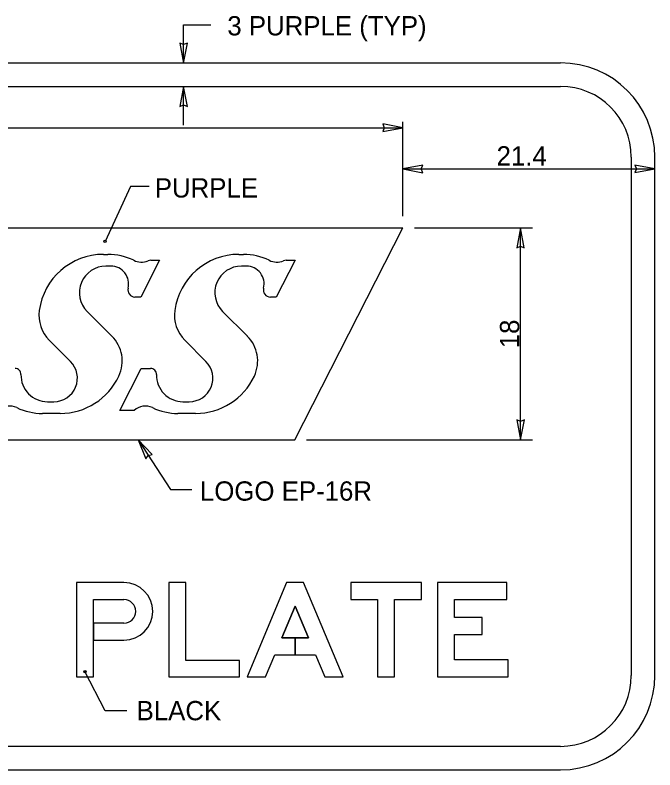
# Model space of a CAD drawing. Extents: x 319706 to 320346, y 1621790 to 1622121.
# Drawn here: x 319803.6 to 319850, y 1621939.2 to 1621994 of the extents above; entities that cross this region are included whole.
import ezdxf

# ---------------------------------------------------------------- set-up
doc = ezdxf.new("R2010")
doc.units = 0
for name, color, linetype in [('1', 7, 'Continuous'), ('52', 7, 'Continuous'), ('GSBWFill', 7, 'Continuous'), ('GSColorFill', 7, 'Continuous'), ('GSOutline', 7, 'Continuous'), ('SignPanel', 7, 'Continuous')]:
    doc.layers.add(name, color=color, linetype=linetype)

msp = doc.modelspace()

# ---------------------------------------------------------------- linework, layer by layer
at = {"layer": '1'}
for p, q in [((319815.814, 1621993.311), (319817.798, 1621993.298)), ((319815.814, 1621990.526), (319815.814, 1621993.311)), ((319815.814, 1621986.016), (319815.814, 1621988.829)), ((319831.717, 1621979.425), (319831.717, 1621986.265)), ((319794.612, 1621985.838), (319831.717, 1621985.838)), ((319831.717, 1621982.845), (319850.014, 1621982.845)), ((319811.95, 1621981.567), (319810.107, 1621977.589)), ((319813.308, 1621981.567), (319811.95, 1621981.567)), ((319832.572, 1621978.569), (319841.122, 1621978.569)), ((319840.267, 1621963.179), (319840.267, 1621978.569)), ((319812.512, 1621963.179), (319814.868, 1621959.581)), ((319824.73, 1621963.179), (319841.122, 1621963.179)), ((319814.868, 1621959.581), (319816.416, 1621959.581)), ((319810.118, 1621943.512), (319808.646, 1621946.366)), ((319811.68, 1621943.512), (319810.118, 1621943.512))]:
    msp.add_line(p, q, dxfattribs=at)
for centre in [(319810.107, 1621977.588), (319808.646, 1621946.366)]:
    msp.add_circle(centre, 0.0855, dxfattribs=at)
at = {"layer": '52'}
for p, q in [((319815.814, 1621991.866), (319815.544, 1621991.976)), ((319815.544, 1621991.976), (319815.814, 1621990.526)), ((319815.814, 1621990.526), (319816.094, 1621991.976)), ((319816.094, 1621991.976), (319815.814, 1621991.866)), ((319815.814, 1621988.829), (319815.534, 1621987.379)), ((319816.084, 1621987.379), (319815.814, 1621988.829)), ((319815.534, 1621987.379), (319815.814, 1621987.489)), ((319815.814, 1621987.489), (319816.084, 1621987.379)), ((319831.717, 1621985.838), (319830.267, 1621986.118)), ((319830.267, 1621986.118), (319830.377, 1621985.838)), ((319830.377, 1621985.838), (319830.267, 1621985.568)), ((319830.267, 1621985.568), (319831.717, 1621985.838)), ((319833.167, 1621983.115), (319831.717, 1621982.845)), ((319833.057, 1621982.845), (319833.167, 1621983.115)), ((319850.014, 1621982.845), (319848.564, 1621983.125)), ((319848.564, 1621983.125), (319848.674, 1621982.845)), ((319831.717, 1621982.845), (319833.167, 1621982.565)), ((319833.167, 1621982.565), (319833.057, 1621982.845)), ((319848.674, 1621982.845), (319848.564, 1621982.575)), ((319848.564, 1621982.575), (319850.014, 1621982.845)), ((319840.267, 1621978.569), (319839.987, 1621977.119)), ((319840.537, 1621977.119), (319840.267, 1621978.569)), ((319839.987, 1621977.119), (319840.267, 1621977.229)), ((319840.267, 1621977.229), (319840.537, 1621977.119)), ((319840.267, 1621964.519), (319839.997, 1621964.629)), ((319839.997, 1621964.629), (319840.267, 1621963.179)), ((319840.267, 1621963.179), (319840.547, 1621964.629)), ((319840.547, 1621964.629), (319840.267, 1621964.519)), ((319812.512, 1621963.179), (319813.072, 1621961.813)), ((319813.532, 1621962.114), (319812.512, 1621963.179)), ((319813.072, 1621961.813), (319813.246, 1621962.058)), ((319813.246, 1621962.058), (319813.532, 1621962.114))]:
    msp.add_line(p, q, dxfattribs=at)
at = {"layer": 'GSBWFill'}
msp.add_line((319809.262, 1621951.598), (319811.485, 1621951.598), dxfattribs=at)
for points in [[(319811.485, 1621952.829), (319808.03, 1621952.829), (319808.03, 1621945.988), (319809.262, 1621945.988), (319809.262, 1621951.598)], [(319811.485, 1621949.887), (319809.262, 1621949.887), (319809.262, 1621948.656), (319811.485, 1621948.656)]]:
    msp.add_lwpolyline(points, dxfattribs=at)
for points in [[(319819.866, 1621945.988), (319819.866, 1621947.185), (319815.966, 1621947.185), (319815.966, 1621952.829), (319814.735, 1621952.829), (319814.735, 1621945.988)], [(319824.864, 1621948.827), (319823.903, 1621948.827), (319823.903, 1621947.595), (319825.381, 1621947.595), (319826.056, 1621945.988), (319827.392, 1621945.988), (319824.518, 1621952.829), (319823.287, 1621952.829), (319820.413, 1621945.988), (319821.749, 1621945.988), (319822.424, 1621947.595), (319823.903, 1621947.595), (319823.903, 1621948.827), (319822.942, 1621948.827), (319823.903, 1621951.115)], [(319827.939, 1621951.598), (319829.889, 1621951.598), (319829.889, 1621945.988), (319831.121, 1621945.988), (319831.121, 1621951.598), (319833.07, 1621951.598), (319833.07, 1621952.829), (319827.939, 1621952.829)], [(319839.365, 1621947.219), (319835.465, 1621947.219), (319835.465, 1621949.059), (319837.483, 1621949.059), (319837.483, 1621950.291), (319835.465, 1621950.291), (319835.465, 1621951.598), (319839.262, 1621951.598), (319839.262, 1621952.829), (319834.233, 1621952.829), (319834.233, 1621945.988), (319839.365, 1621945.988)]]:
    msp.add_lwpolyline(points, close=True, dxfattribs=at)
for major_axis in [(0, 2.087), (0, 0.855)]:
    msp.add_ellipse((319811.485, 1621950.742), major_axis=major_axis, ratio=0.999994, start_param=3.141593, end_param=6.283185, dxfattribs=at)
at = {"layer": 'GSColorFill'}
msp.add_line((319809.262, 1621951.598), (319811.485, 1621951.598), dxfattribs=at)
for points in [[(319811.485, 1621952.829), (319808.03, 1621952.829), (319808.03, 1621945.988), (319809.262, 1621945.988), (319809.262, 1621951.598)], [(319811.485, 1621949.887), (319809.262, 1621949.887), (319809.262, 1621948.656), (319811.485, 1621948.656)]]:
    msp.add_lwpolyline(points, dxfattribs=at)
for points in [[(319819.866, 1621945.988), (319819.866, 1621947.185), (319815.966, 1621947.185), (319815.966, 1621952.829), (319814.735, 1621952.829), (319814.735, 1621945.988)], [(319824.864, 1621948.827), (319823.903, 1621948.827), (319823.903, 1621947.595), (319825.381, 1621947.595), (319826.056, 1621945.988), (319827.392, 1621945.988), (319824.518, 1621952.829), (319823.287, 1621952.829), (319820.413, 1621945.988), (319821.749, 1621945.988), (319822.424, 1621947.595), (319823.903, 1621947.595), (319823.903, 1621948.827), (319822.942, 1621948.827), (319823.903, 1621951.115)], [(319827.939, 1621951.598), (319829.889, 1621951.598), (319829.889, 1621945.988), (319831.121, 1621945.988), (319831.121, 1621951.598), (319833.07, 1621951.598), (319833.07, 1621952.829), (319827.939, 1621952.829)], [(319839.365, 1621947.219), (319835.465, 1621947.219), (319835.465, 1621949.059), (319837.483, 1621949.059), (319837.483, 1621950.291), (319835.465, 1621950.291), (319835.465, 1621951.598), (319839.262, 1621951.598), (319839.262, 1621952.829), (319834.233, 1621952.829), (319834.233, 1621945.988), (319839.365, 1621945.988)]]:
    msp.add_lwpolyline(points, close=True, dxfattribs=at)
for major_axis in [(0, 2.087), (0, 0.855)]:
    msp.add_ellipse((319811.485, 1621950.742), major_axis=major_axis, ratio=0.999994, start_param=3.141593, end_param=6.283185, dxfattribs=at)
at = {"layer": 'GSOutline'}
for p, q in [((319809.262, 1621951.598), (319811.485, 1621951.598)), ((319809.262, 1621948.656), (319811.485, 1621948.656))]:
    msp.add_line(p, q, dxfattribs=at)
for points in [[(319811.485, 1621952.829), (319808.03, 1621952.829), (319808.03, 1621945.988), (319809.262, 1621945.988), (319809.262, 1621948.656)], [(319811.485, 1621949.887), (319809.262, 1621949.887), (319809.262, 1621951.598)]]:
    msp.add_lwpolyline(points, dxfattribs=at)
for points in [[(319819.866, 1621945.988), (319819.866, 1621947.185), (319815.966, 1621947.185), (319815.966, 1621952.829), (319814.735, 1621952.829), (319814.735, 1621945.988)], [(319822.424, 1621947.595), (319825.381, 1621947.595), (319826.056, 1621945.988), (319827.392, 1621945.988), (319824.518, 1621952.829), (319823.287, 1621952.829), (319820.413, 1621945.988), (319821.749, 1621945.988)], [(319827.939, 1621951.598), (319829.889, 1621951.598), (319829.889, 1621945.988), (319831.121, 1621945.988), (319831.121, 1621951.598), (319833.07, 1621951.598), (319833.07, 1621952.829), (319827.939, 1621952.829)], [(319839.365, 1621947.219), (319835.465, 1621947.219), (319835.465, 1621949.059), (319837.483, 1621949.059), (319837.483, 1621950.291), (319835.465, 1621950.291), (319835.465, 1621951.598), (319839.262, 1621951.598), (319839.262, 1621952.829), (319834.233, 1621952.829), (319834.233, 1621945.988), (319839.365, 1621945.988)], [(319824.864, 1621948.827), (319823.903, 1621951.115), (319822.942, 1621948.827)]]:
    msp.add_lwpolyline(points, close=True, dxfattribs=at)
for major_axis in [(0, 2.087), (0, 0.855)]:
    msp.add_ellipse((319811.485, 1621950.742), major_axis=major_axis, ratio=0.999994, start_param=3.141593, end_param=6.283185, dxfattribs=at)
at = {"layer": 'SignPanel'}
for p, q in [((319733.734, 1621990.539), (319843.174, 1621990.539)), ((319733.734, 1621988.829), (319843.174, 1621988.829)), ((319848.304, 1621946.079), (319848.304, 1621983.699)), ((319850.014, 1621946.079), (319850.014, 1621983.699)), ((319782.943, 1621978.569), (319831.717, 1621978.569)), ((319823.875, 1621963.179), (319831.717, 1621978.569)), ((319809.997, 1621976.645), (319810.321, 1621976.645)), ((319819.83, 1621976.645), (319820.154, 1621976.645)), ((319814.064, 1621976.217), (319812.705, 1621973.551)), ((319813.423, 1621976.217), (319814.064, 1621976.217)), ((319823.897, 1621976.217), (319822.538, 1621973.551)), ((319823.255, 1621976.217), (319823.897, 1621976.217)), ((319810.538, 1621975.79), (319810.172, 1621975.79)), ((319820.371, 1621975.79), (319820.004, 1621975.79)), ((319812.705, 1621973.551), (319812.278, 1621973.551)), ((319822.538, 1621973.551), (319822.11, 1621973.551)), ((319808.811, 1621972.506), (319810.603, 1621970.714)), ((319818.644, 1621972.506), (319820.436, 1621970.714)), ((319807.603, 1621968.877), (319806.065, 1621970.415)), ((319817.436, 1621968.877), (319815.898, 1621970.415)), ((319811.175, 1621965.317), (319812.728, 1621968.364)), ((319812.728, 1621968.364), (319813.415, 1621968.364)), ((319805.932, 1621965.957), (319806.394, 1621965.957)), ((319815.765, 1621965.957), (319816.226, 1621965.957)), ((319806.854, 1621965.102), (319805.568, 1621965.102)), ((319812.214, 1621965.317), (319811.175, 1621965.317)), ((319816.686, 1621965.102), (319815.4, 1621965.102)), ((319781.809, 1621963.179), (319823.875, 1621963.179)), ((319733.734, 1621940.949), (319843.174, 1621940.949)), ((319733.734, 1621939.239), (319843.174, 1621939.239))]:
    msp.add_line(p, q, dxfattribs=at)
for centre, radius, start, end in [((319843.173, 1621983.698), 6.84, 0, 90), ((319843.173, 1621983.698), 5.13, 0, 90), ((319809.997, 1621971.942), 4.702, 90, 172.3089), ((319810.321, 1621972.369), 4.275, 64.0896, 90), ((319819.829, 1621971.942), 4.702, 90, 172.3089), ((319820.153, 1621972.369), 4.275, 64.0896, 90), ((319812.749, 1621977.368), 1.282, 244.0896, 292.0347), ((319813.423, 1621975.704), 0.513, 90, 112.0347), ((319822.582, 1621977.368), 1.282, 244.0896, 292.0347), ((319823.255, 1621975.704), 0.513, 90, 112.0347), ((319810.171, 1621973.865), 1.924, 90, 225), ((319810.538, 1621974.507), 1.282, 345.6915, 90), ((319820.004, 1621973.865), 1.924, 90, 225), ((319820.371, 1621974.507), 1.282, 345.6915, 90), ((319812.278, 1621974.063), 0.513, 165.6915, 270), ((319822.111, 1621974.063), 0.513, 165.6915, 270), ((319807.878, 1621972.228), 2.565, 172.3089, 225), ((319817.711, 1621972.228), 2.565, 172.3089, 225), ((319808.79, 1621968.899), 2.565, 334.95, 45), ((319818.622, 1621968.899), 2.565, 334.95, 45), ((319806.394, 1621967.667), 1.71, 270, 45), ((319816.226, 1621967.667), 1.71, 270, 45), ((319803.582, 1621967.935), 0.427, 358.6664, 90), ((319813.414, 1621967.935), 0.427, 358.6664, 90), ((319805.933, 1621967.88), 1.924, 178.6665, 270), ((319806.853, 1621969.804), 4.702, 270, 334.95), ((319815.765, 1621967.88), 1.924, 178.6665, 270), ((319816.686, 1621969.804), 4.702, 270, 334.95), ((319803.201, 1621964.443), 1.197, 64.3795, 133.1892), ((319805.567, 1621969.377), 4.275, 244.3795, 270), ((319813.033, 1621964.443), 1.197, 64.3795, 133.1892), ((319815.399, 1621969.377), 4.275, 244.3795, 270), ((319843.173, 1621946.078), 6.84, 270, 360), ((319843.173, 1621946.078), 5.13, 270, 0)]:
    msp.add_arc(centre, radius, start, end, dxfattribs=at)

# ---------------------------------------------------------------- texts
at = {"layer": '1'}
for s, p in [('3 PURPLE (TYP)', (319818.986, 1621992.532)), ('21.4', (319838.524, 1621983.09)), ('PURPLE', (319813.719, 1621980.768)), ('LOGO EP-16R', (319816.997, 1621958.774)), ('BLACK', (319812.4, 1621942.84))]:
    msp.add_text(s, height=1.4, dxfattribs=at).set_placement(p)
msp.add_text('18', height=1.4, rotation=90, dxfattribs=at).set_placement((319840.167, 1621969.831))

doc.saveas('drawing.dxf')
